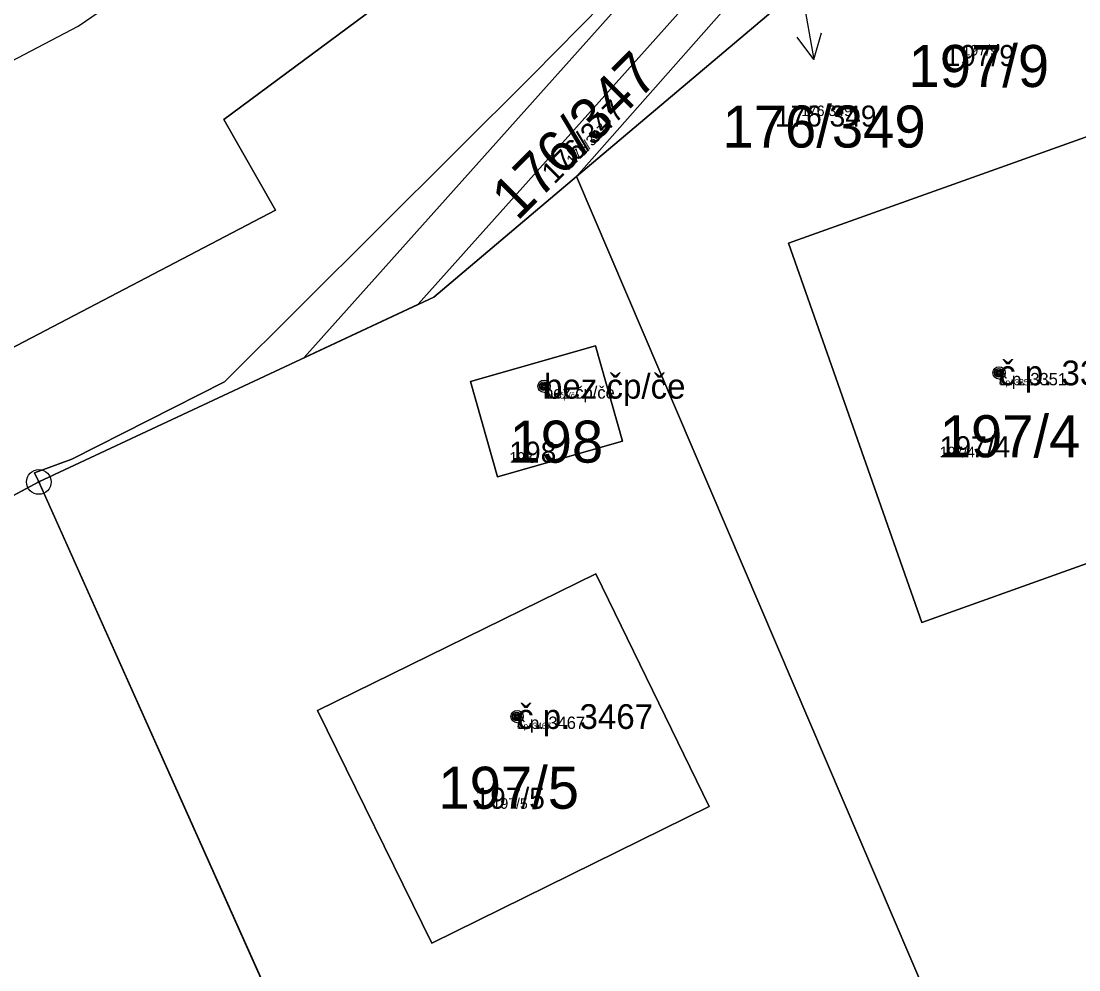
# Model space of a CAD drawing. Extents: x -759873 to -758487, y -975024 to -973516.
# Drawn here: x -759216.9 to -759174.11, y -974880.06 to -974841.69 of the extents above; entities that cross this region are included whole.
import ezdxf

# ---------------------------------------------------------------- set-up
doc = ezdxf.new("R2010")
doc.units = 0
for name, color, linetype in [('KAT_02_hranice parcel', 7, 'Continuous'), ('KAT_03_1000_st čísla parcelní', 7, 'Continuous'), ('KAT_03_1000_čísla parcelní', 7, 'Continuous'), ('KAT_03_1000_čísla popisná', 7, 'Continuous'), ('KAT_03_250_st čísla parcelní', 7, 'Continuous'), ('KAT_03_250_čísla parcelní', 7, 'Continuous'), ('KAT_03_250_čísla popisná', 7, 'Continuous'), ('KAT_03_500_st čísla parcelní', 7, 'Continuous'), ('KAT_03_500_čísla parcelní', 7, 'Continuous'), ('KAT_03_500_čísla popisná', 7, 'Continuous'), ('KAT_04_vnitřní kresba', 7, 'Continuous'), ('KAT_07_1000_značky budov', 7, 'Continuous'), ('KAT_07_250_značky budov', 7, 'Continuous'), ('KAT_07_500_značky budov', 7, 'Continuous'), ('KAT_10_věcná břemena', 7, 'Continuous'), ('KAT_11_značky bodu BP', 7, 'Continuous'), ('KAT_12_pomocná šipka', 7, 'Continuous'), ('KAT_14_plocha_budovy', 7, 'Continuous'), ('KAT_14_plocha_pozemek', 7, 'Continuous')]:
    doc.layers.add(name, color=color, linetype=linetype)

msp = doc.modelspace()

# ---------------------------------------------------------------- linework, layer by layer
at = {"layer": 'KAT_02_hranice parcel'}
for p, q in [((-759183.12, -974838.42), (-759194.44, -974847.98)), ((-759167.42, -974911.17), (-759194.44, -974847.98)), ((-759216.19, -974860.33), (-759226.6, -974865.92)), ((-759189.72, -974919.43), (-759216.19, -974860.33))]:
    msp.add_line(p, q, dxfattribs=at)
for points in [[(-759339.46, -974882.78), (-759339.8, -974881.64), (-759332.95, -974877.29), (-759323.1, -974873.6), (-759309.63, -974871.79), (-759306.19, -974871.77), (-759306.31, -974877.26), (-759289.39, -974877.59), (-759275.76, -974876.39), (-759260.46, -974873.03), (-759249.2, -974869.3), (-759236.4, -974863.83), (-759220.29, -974856.48), (-759206.61, -974849.33), (-759208.71, -974845.67), (-759199.03, -974838.5), (-759188.78, -974830.26)], [(-759216.19, -974860.33), (-759216.36, -974859.96), (-759214.86, -974859.41), (-759208.68, -974856.28), (-759196.21, -974843.87), (-759187.6, -974835.12), (-759186.16, -974833.19)], [(-759194.44, -974847.98), (-759185.69, -974838.07), (-759184.13, -974835.84), (-759184.73, -974834.81)], [(-759180.46, -974866.01), (-759185.86, -974850.67), (-759173.66, -974846.32), (-759168.24, -974861.65), (-759180.46, -974866.01)], [(-759194.44, -974847.98), (-759200.21, -974852.85), (-759216.19, -974860.33)], [(-759193.67, -974854.83), (-759192.58, -974858.68), (-759197.63, -974860.12), (-759198.72, -974856.27), (-759193.67, -974854.83)], [(-759189.07, -974873.46), (-759200.29, -974878.98), (-759204.91, -974869.57), (-759193.66, -974864.04), (-759189.07, -974873.46)]]:
    msp.add_lwpolyline(points, dxfattribs=at)
at = {"layer": 'KAT_03_1000_čísla popisná'}
for centre in [(-759177.34, -974855.92), (-759195.75, -974856.46), (-759196.84, -974869.82)]:
    msp.add_circle(centre, 0.25, dxfattribs=at)
at = {"layer": 'KAT_03_250_čísla popisná'}
for centre in [(-759177.34, -974855.92), (-759195.75, -974856.46), (-759196.84, -974869.82)]:
    msp.add_circle(centre, 0.0625, dxfattribs=at)
at = {"layer": 'KAT_03_500_čísla popisná'}
for centre in [(-759177.34, -974855.92), (-759195.75, -974856.46), (-759196.84, -974869.82)]:
    msp.add_circle(centre, 0.125, dxfattribs=at)
at = {"layer": 'KAT_04_vnitřní kresba'}
for p, q in [((-759214.6, -974841.89), (-759202.98, -974833.95)), ((-759225.26, -974847.47), (-759214.6, -974841.89))]:
    msp.add_line(p, q, dxfattribs=at)
at = {"layer": 'KAT_07_1000_značky budov'}
for centre in [(-759177.347, -974855.919), (-759195.757, -974856.459), (-759196.847, -974869.819)]:
    msp.add_circle(centre, 0.175, dxfattribs=at)
at = {"layer": 'KAT_07_250_značky budov'}
for centre in [(-759177.342, -974855.92), (-759195.752, -974856.46), (-759196.842, -974869.82)]:
    msp.add_circle(centre, 0.0437, dxfattribs=at)
at = {"layer": 'KAT_07_500_značky budov'}
for centre in [(-759177.343, -974855.92), (-759195.753, -974856.46), (-759196.843, -974869.82)]:
    msp.add_circle(centre, 0.0875, dxfattribs=at)
at = {"layer": 'KAT_10_věcná břemena'}
msp.add_lwpolyline([(-759183.56, -974830.98), (-759185.6, -974828.77), (-759186.31, -974828), (-759187.79, -974829.35), (-759187.14, -974830.05), (-759186.25, -974831.25), (-759188, -974833.64), (-759187.67, -974835.39), (-759205.45, -974855.3), (-759200.84, -974853.14), (-759185.51, -974835.99), (-759185.88, -974834.12)], close=True, dxfattribs=at)
at = {"layer": 'KAT_11_značky bodu BP'}
for radius in [0.5, 0.0303]:
    msp.add_circle((-759216.19, -974860.33), radius, dxfattribs=at)
at = {"layer": 'KAT_12_pomocná šipka'}
for p, q in [((-759185.36, -974840.28), (-759184.839, -974843.235)), ((-759184.839, -974843.235), (-759185.506, -974842.336)), ((-759184.839, -974843.235), (-759184.52, -974842.162))]:
    msp.add_line(p, q, dxfattribs=at)
at = {"layer": 'KAT_14_plocha_budovy'}
for points in [[(-759185.86, -974850.67), (-759180.46, -974866.01), (-759168.24, -974861.65), (-759173.66, -974846.32)], [(-759193.67, -974854.83), (-759198.72, -974856.27), (-759197.63, -974860.12), (-759192.58, -974858.68)], [(-759193.66, -974864.04), (-759204.91, -974869.57), (-759200.29, -974878.98), (-759189.07, -974873.46)]]:
    msp.add_lwpolyline(points, close=True, dxfattribs=at)
at = {"layer": 'KAT_14_plocha_pozemek'}
for points in [[(-759306.31, -974877.26), (-759289.39, -974877.59), (-759275.76, -974876.39), (-759260.46, -974873.03), (-759249.2, -974869.3), (-759236.4, -974863.83), (-759220.29, -974856.48), (-759206.61, -974849.33), (-759208.71, -974845.67), (-759199.03, -974838.5), (-759188.78, -974830.26), (-759183.17, -974825.13), (-759182.08, -974824.14), (-759181.15, -974823.29), (-759171.83, -974813.43)], [(-759309.62, -974881.37), (-759294.63, -974881.97), (-759273.68, -974881.15), (-759273.27, -974884.11), (-759238.51, -974872.32), (-759226.6, -974865.92), (-759216.19, -974860.33), (-759216.36, -974859.96), (-759214.86, -974859.41), (-759208.68, -974856.28), (-759196.21, -974843.87), (-759187.6, -974835.12), (-759186.16, -974833.19), (-759188.78, -974830.26), (-759199.03, -974838.5), (-759208.71, -974845.67), (-759206.61, -974849.33), (-759220.29, -974856.48), (-759236.4, -974863.83), (-759249.2, -974869.3), (-759260.46, -974873.03), (-759275.76, -974876.39), (-759289.39, -974877.59), (-759306.31, -974877.26)]]:
    msp.add_lwpolyline(points, dxfattribs=at)
for points in [[(-759183.12, -974838.42), (-759183.83, -974836.16), (-759178.53, -974834.55), (-759176.83, -974833.12), (-759177.99, -974830.01), (-759182.08, -974824.14), (-759183.17, -974825.13), (-759179.25, -974830.66), (-759178.65, -974832.39), (-759179, -974833.07), (-759184.73, -974834.81), (-759184.13, -974835.84), (-759185.69, -974838.07), (-759194.44, -974847.98)], [(-759178.07, -974834.41), (-759176.83, -974838.48), (-759182.55, -974840.22), (-759183.12, -974838.42), (-759194.44, -974847.98), (-759167.42, -974911.17), (-759145.92, -974903.21), (-759159.23, -974872.41), (-759176.11, -974832.51), (-759176.83, -974833.12), (-759178.53, -974834.55)], [(-759194.44, -974847.98), (-759185.69, -974838.07), (-759184.13, -974835.84), (-759184.73, -974834.81), (-759186.16, -974833.19), (-759187.6, -974835.12), (-759196.21, -974843.87), (-759208.68, -974856.28), (-759214.86, -974859.41), (-759216.36, -974859.96), (-759216.19, -974860.33), (-759200.21, -974852.85)], [(-759180.46, -974866.01), (-759185.86, -974850.67), (-759173.66, -974846.32), (-759168.24, -974861.65)], [(-759180.46, -974866.01), (-759168.24, -974861.65), (-759173.66, -974846.32), (-759185.86, -974850.67)], [(-759194.44, -974847.98), (-759200.21, -974852.85), (-759216.19, -974860.33), (-759189.72, -974919.43), (-759167.42, -974911.17)], [(-759193.67, -974854.83), (-759198.72, -974856.27), (-759197.63, -974860.12), (-759192.58, -974858.68)], [(-759193.67, -974854.83), (-759192.58, -974858.68), (-759197.63, -974860.12), (-759198.72, -974856.27)], [(-759216.19, -974860.33), (-759226.6, -974865.92), (-759217.66, -974889.98), (-759216.48, -974893.8), (-759203.97, -974928.37), (-759188.86, -974921.74), (-759189.72, -974919.43)], [(-759189.07, -974873.46), (-759200.29, -974878.98), (-759204.91, -974869.57), (-759193.66, -974864.04)], [(-759189.07, -974873.46), (-759193.66, -974864.04), (-759204.91, -974869.57), (-759200.29, -974878.98)]]:
    msp.add_lwpolyline(points, close=True, dxfattribs=at)

# ---------------------------------------------------------------- texts
at = {"layer": 'KAT_03_1000_st čísla parcelní'}
for s, p in [('197/9', (-759181.003, -974844.353)), ('198', (-759197.15, -974859.549)), ('197/4', (-759179.74, -974859.33)), ('197/5', (-759200.023, -974873.549))]:
    msp.add_text(s, height=1.7, dxfattribs=at).set_placement(p)
at = {"layer": 'KAT_03_1000_čísla parcelní'}
msp.add_text('176/347', height=1.7, rotation=45, dxfattribs=at).set_placement((-759196.832, -974849.804))
msp.add_text('176/349', height=1.7, dxfattribs=at).set_placement((-759188.528, -974846.803))
at = {"layer": 'KAT_03_1000_čísla popisná'}
for s, p in [('č.p. 3351', (-759177.34, -974856.42)), ('bez čp/če', (-759195.75, -974856.96)), ('č.p. 3467', (-759196.84, -974870.32))]:
    msp.add_text(s, height=1, dxfattribs=at).set_placement(p)
at = {"layer": 'KAT_03_250_st čísla parcelní'}
for s, p in [('197/9', (-759178.815, -974843.078)), ('198', (-759197.15, -974859.549)), ('197/4', (-759179.74, -974859.33)), ('197/5', (-759197.831, -974873.549))]:
    msp.add_text(s, height=0.425, dxfattribs=at).set_placement(p)
at = {"layer": 'KAT_03_250_čísla parcelní'}
msp.add_text('176/349', height=0.425, dxfattribs=at).set_placement((-759185.349, -974845.528))
msp.add_text('176/347', height=0.425, rotation=45, dxfattribs=at).set_placement((-759194.585, -974847.557))
at = {"layer": 'KAT_03_250_čísla popisná'}
for s, p in [('č.p. 3351', (-759177.34, -974856.42)), ('bez čp/če', (-759195.75, -974856.96)), ('č.p. 3467', (-759196.84, -974870.32))]:
    msp.add_text(s, height=0.25, dxfattribs=at).set_placement(p)
at = {"layer": 'KAT_03_500_st čísla parcelní'}
for s, p in [('197/9', (-759179.544, -974843.503)), ('198', (-759197.15, -974859.549)), ('197/4', (-759179.74, -974859.33)), ('197/5', (-759198.561, -974873.549))]:
    msp.add_text(s, height=0.85, dxfattribs=at).set_placement(p)
at = {"layer": 'KAT_03_500_čísla parcelní'}
msp.add_text('176/347', height=0.85, rotation=45, dxfattribs=at).set_placement((-759195.334, -974848.306))
msp.add_text('176/349', height=0.85, dxfattribs=at).set_placement((-759186.409, -974845.953))
at = {"layer": 'KAT_03_500_čísla popisná'}
for s, p in [('č.p. 3351', (-759177.34, -974856.42)), ('bez čp/če', (-759195.75, -974856.96)), ('č.p. 3467', (-759196.84, -974870.32))]:
    msp.add_text(s, height=0.5, dxfattribs=at).set_placement(p)

doc.saveas('drawing.dxf')
